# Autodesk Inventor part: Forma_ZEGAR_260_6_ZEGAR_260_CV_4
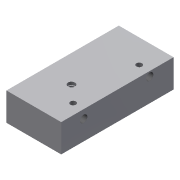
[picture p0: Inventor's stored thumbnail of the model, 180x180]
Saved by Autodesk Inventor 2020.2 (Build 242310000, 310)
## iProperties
Created: 2015-01
Part Number: Forma_ZEGAR_260_6_ZEGAR_260_CV_4
Material: Ogólny
Document SubType Name: Modeling
Designer: F.Stasiak
Density: 1 g/cm^3
Appearance: Domyślna
Catalog Web Link: www.expertbooks.pl
Manager: www.cadconsulting.pl
Company: Fabian Stasiak CAD Consulting
Author: F.Stasiak
Subject: Zbiór ćwiczeń. Autodesk Inventor 2020. Kurs Professional
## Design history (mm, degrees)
node "Forma_ZEGAR_260_4_ZEGAR_260_CV_Base"
feature "Rzeźbienie4"
feature "Gwint1" dims "d0" = 0, "d1" = 0
feature "Rzeźbienie7"
feature "Gwint4" dims "d6" = 0, "d7" = 0
feature "Rzeźbienie9"
feature "Rzeźbienie12"
feature "Bryła1::Forma_ZEGAR_260_4_ZEGAR_260_CV_Base"
tag "Bryła wyprowadzona1"
node "Bryła1"
feature "Forma_ZEGAR_260_4_ZEGAR_260_CV_Base_Bodies"
feature "Powierzchnia4"
body "Srf4"
feature "Powierzchnia7"
body "Srf7"
feature "Powierzchnia9"
body "Srf9"
feature "Powierzchnia12"
body "Srf12"
